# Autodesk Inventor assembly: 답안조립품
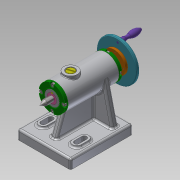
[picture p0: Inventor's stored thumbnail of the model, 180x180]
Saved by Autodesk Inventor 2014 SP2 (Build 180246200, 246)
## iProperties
Created: 2022-06
Part Number: 답안조립품
Document SubType Name: Assembly
Designer: 거성
Author: 거성
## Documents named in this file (18)
- C:\Users\거성\Desktop\720606V1004\답안조립품.iam
- C:\Users\거성\Desktop\720606V1004\본체.ipt
- C:\Users\거성\Desktop\720606V1004\슬리브.ipt
- C:\Users\거성\Desktop\720606V1004\중공축.ipt
- C:\Users\거성\Desktop\720606V1004\커버.ipt
- C:\Users\거성\Desktop\720606V1004\센터.ipt
- C:\Users\거성\Desktop\720606V1004\센터홀더.ipt
- C:\Users\거성\Desktop\720606V1004\볼트 M3.ipt
- C:\Users\거성\Desktop\720606V1004\부시.ipt
- C:\Users\거성\Desktop\720606V1004\나사.ipt
- C:\Users\거성\Desktop\720606V1004\나사축.ipt
- C:\Users\거성\Desktop\720606V1004\키 4 x 4 x 10.ipt
- C:\Users\거성\Desktop\720606V1004\멈춤나사 M3.ipt
- C:\Users\거성\Desktop\720606V1004\플랜지.ipt
- C:\Users\거성\Desktop\720606V1004\돌림판.ipt
- C:\Users\거성\Desktop\720606V1004\너트 M8.ipt
- C:\Users\거성\Desktop\720606V1004\와셔.ipt
- C:\Users\거성\Desktop\720606V1004\핸들.ipt
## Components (2 placed, 2 different names)
1. 플랜지:1 — 각도:2
2. 핸들:1
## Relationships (1: Angle 1)
- 각도:2 [Angle]: 플랜지:1
